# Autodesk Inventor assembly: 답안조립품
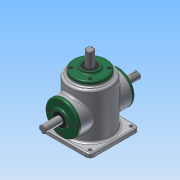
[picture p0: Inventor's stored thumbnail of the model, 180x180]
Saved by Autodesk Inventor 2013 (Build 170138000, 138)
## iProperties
Created: 2015-10
Part Number: 답안조립품
Document SubType Name: Assembly
Designer: Administrator
Author: Administrator
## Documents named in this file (14)
- C:\Users\Administrator\Desktop\451008V1017\답안조립품.iam
- C:\Users\Administrator\Desktop\451008V1017\본체.ipt
- C:\Users\Administrator\Desktop\451008V1017\커버.ipt
- C:\Users\Administrator\Desktop\451008V1017\베어링 6203.ipt
- C:\Users\Administrator\Desktop\451008V1017\오일실.ipt
- C:\Users\Administrator\Desktop\451008V1017\메인 축.ipt
- 메인 축.ipt
- C:\Users\Administrator\Desktop\451008V1017\키 5x5.ipt
- C:\Users\Administrator\Desktop\451008V1017\메인 베벨기어.ipt
- C:\Users\Administrator\Desktop\451008V1017\서브 축.ipt
- 서브 축.ipt
- C:\Users\Administrator\Desktop\451008V1017\키 4x4.ipt
- C:\Users\Administrator\Desktop\451008V1017\서브 베벨기어.ipt
- C:\Users\Administrator\Desktop\451008V1017\M4.ipt
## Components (12 placed, 1 different names)
1. M4:1
2. M4:2
3. M4:3
4. M4:4
5. M4:5
6. M4:6
7. M4:7
8. M4:8
9. M4:9
10. M4:10
11. M4:11
12. M4:12
